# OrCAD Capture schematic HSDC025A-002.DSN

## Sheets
1 PAGE1: title: TUSB1064RNQEVM Block; rev: A; note: HSDC025A-002
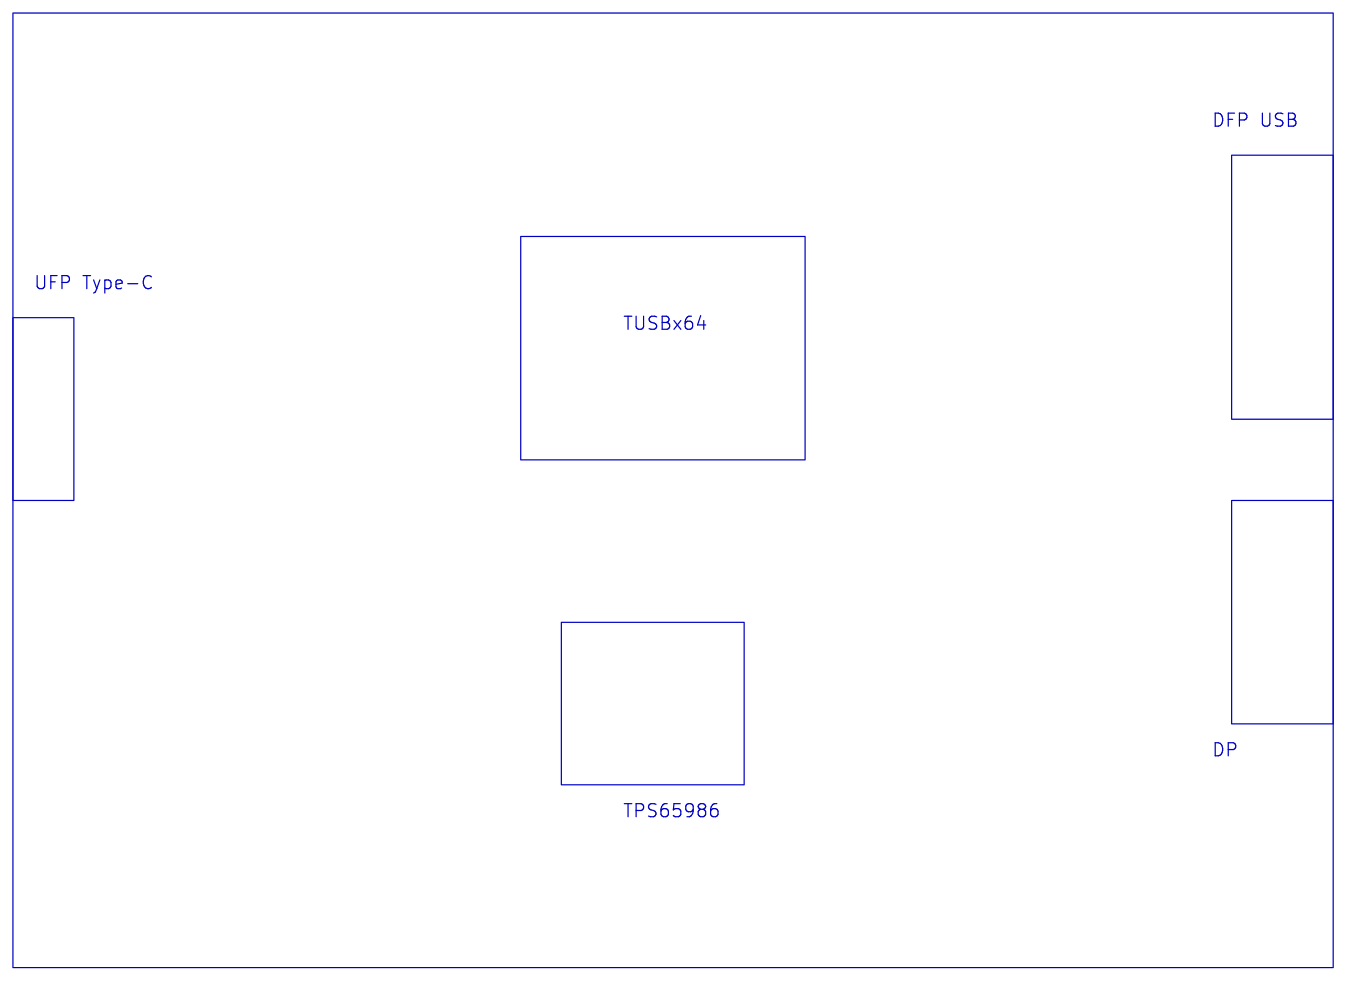
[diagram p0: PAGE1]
2 PAGE2: size B; title: TUSB1064RNQ
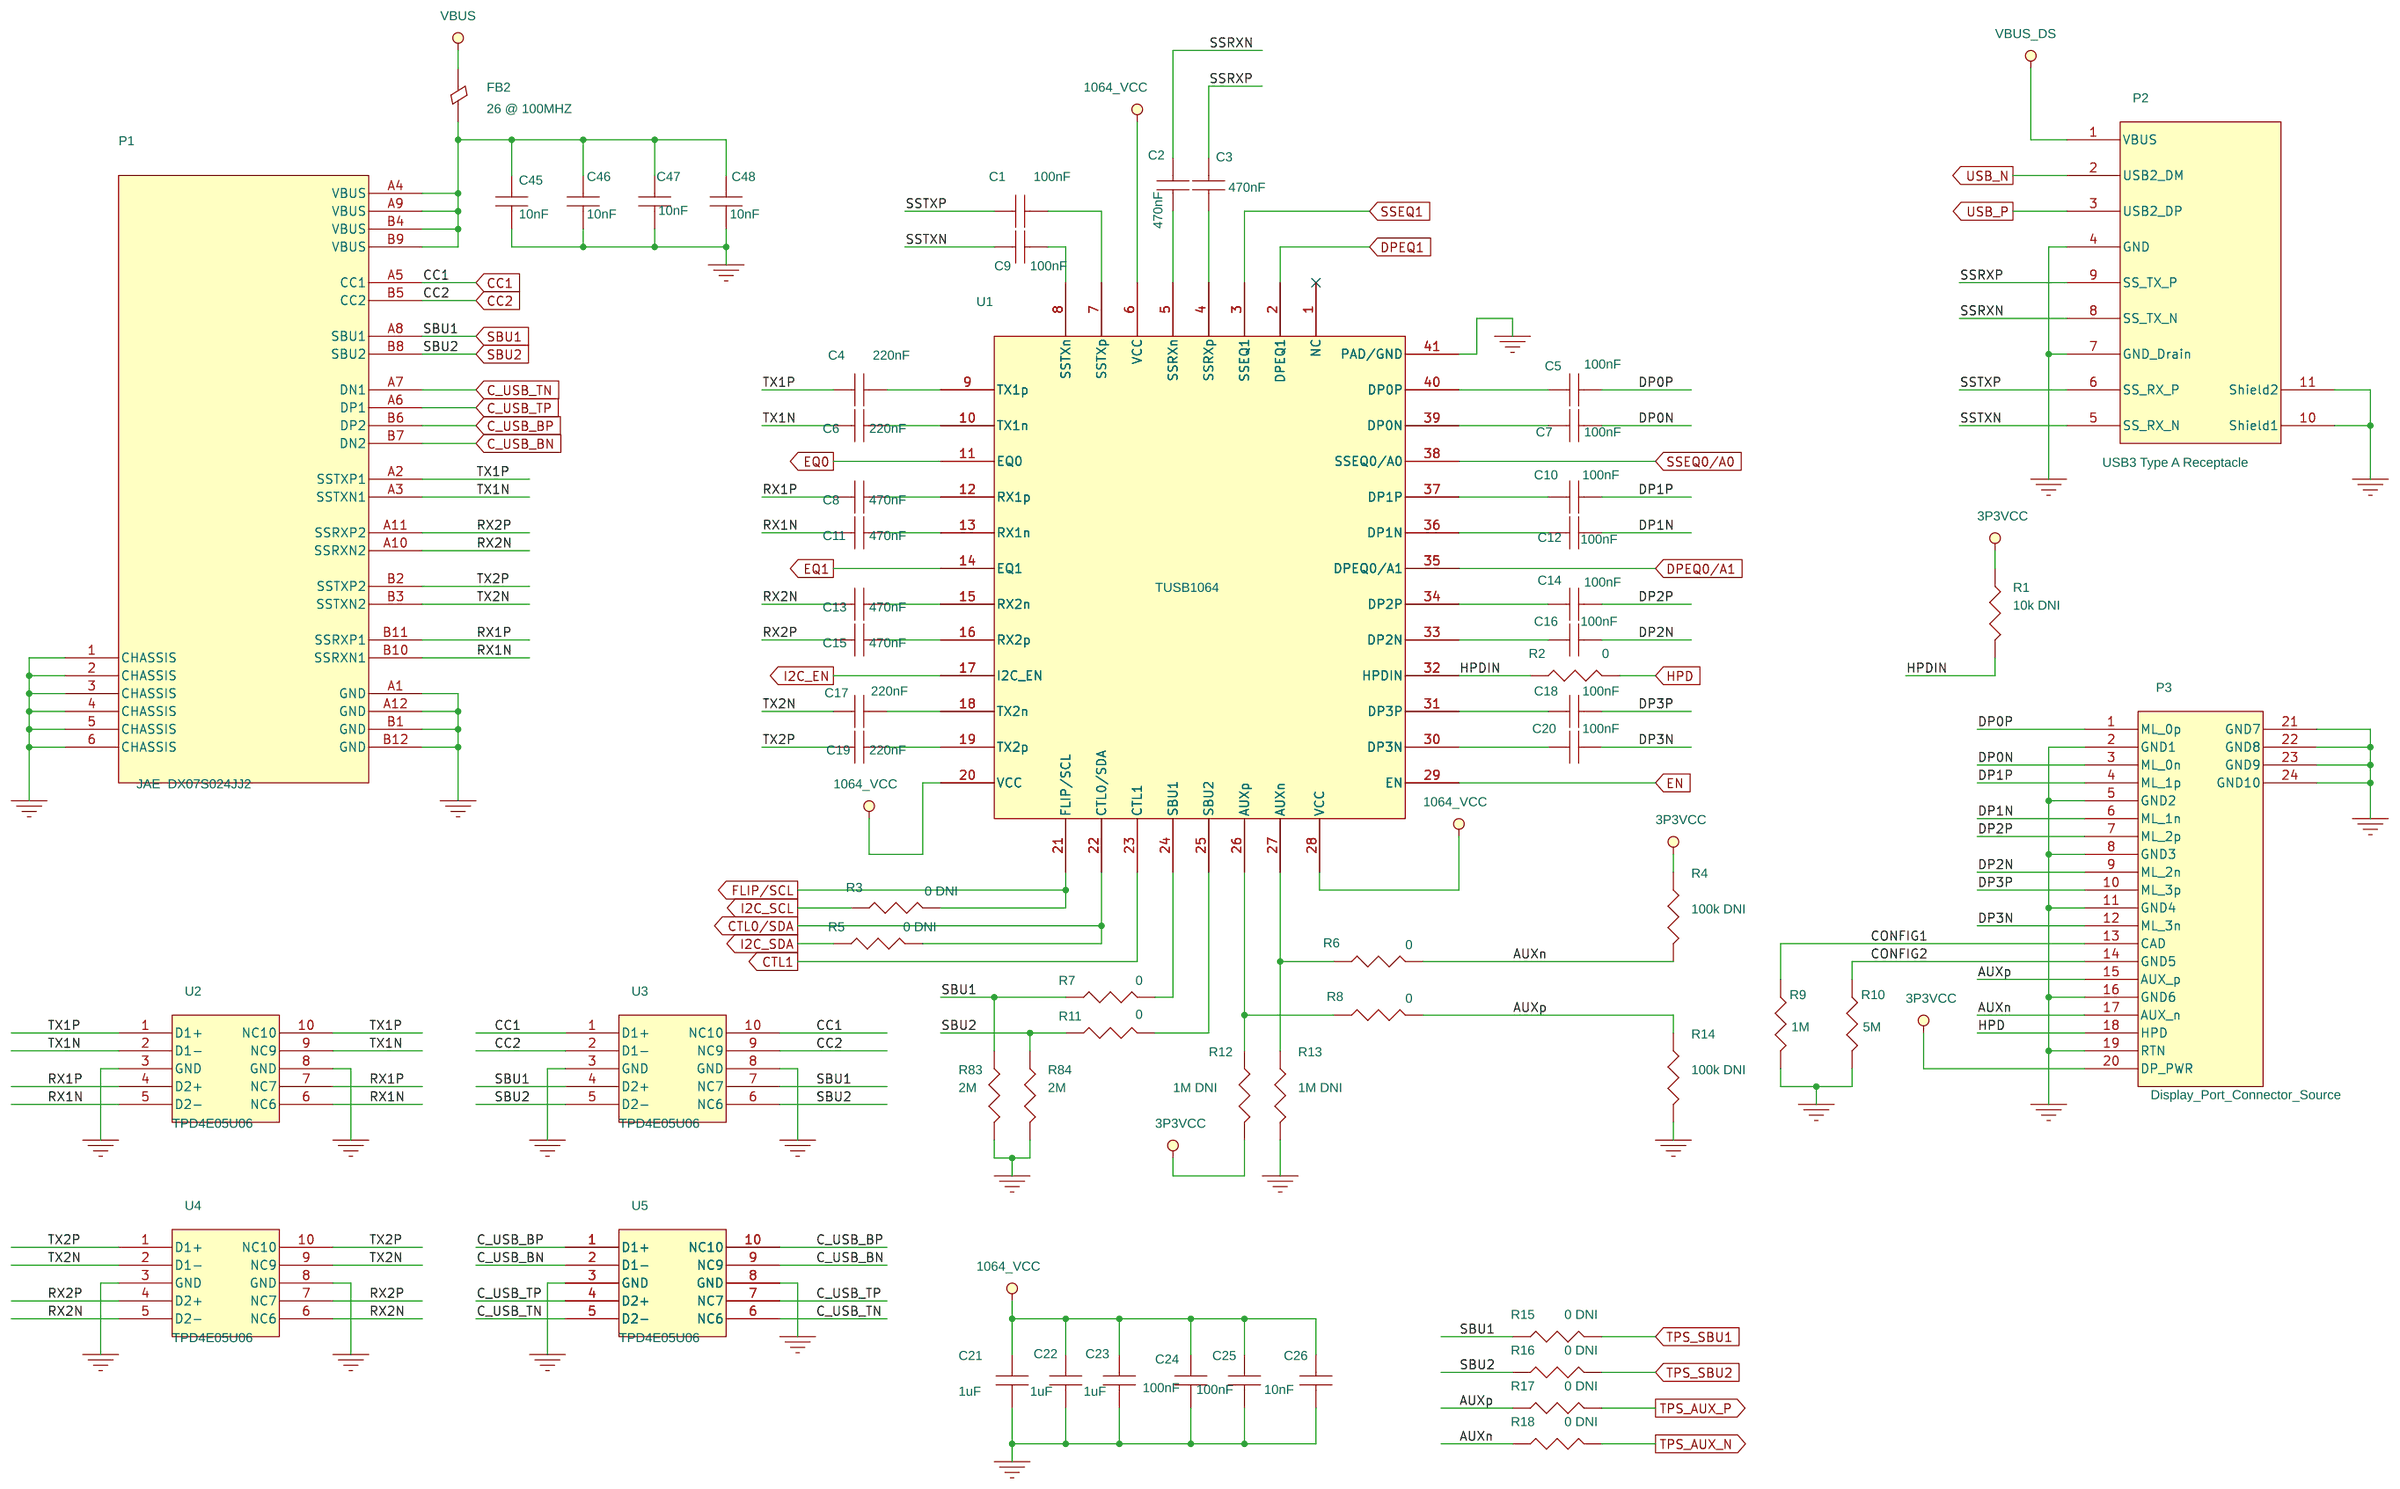
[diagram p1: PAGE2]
3 PAGE3: size B; title: TUSB1064 Config Pins
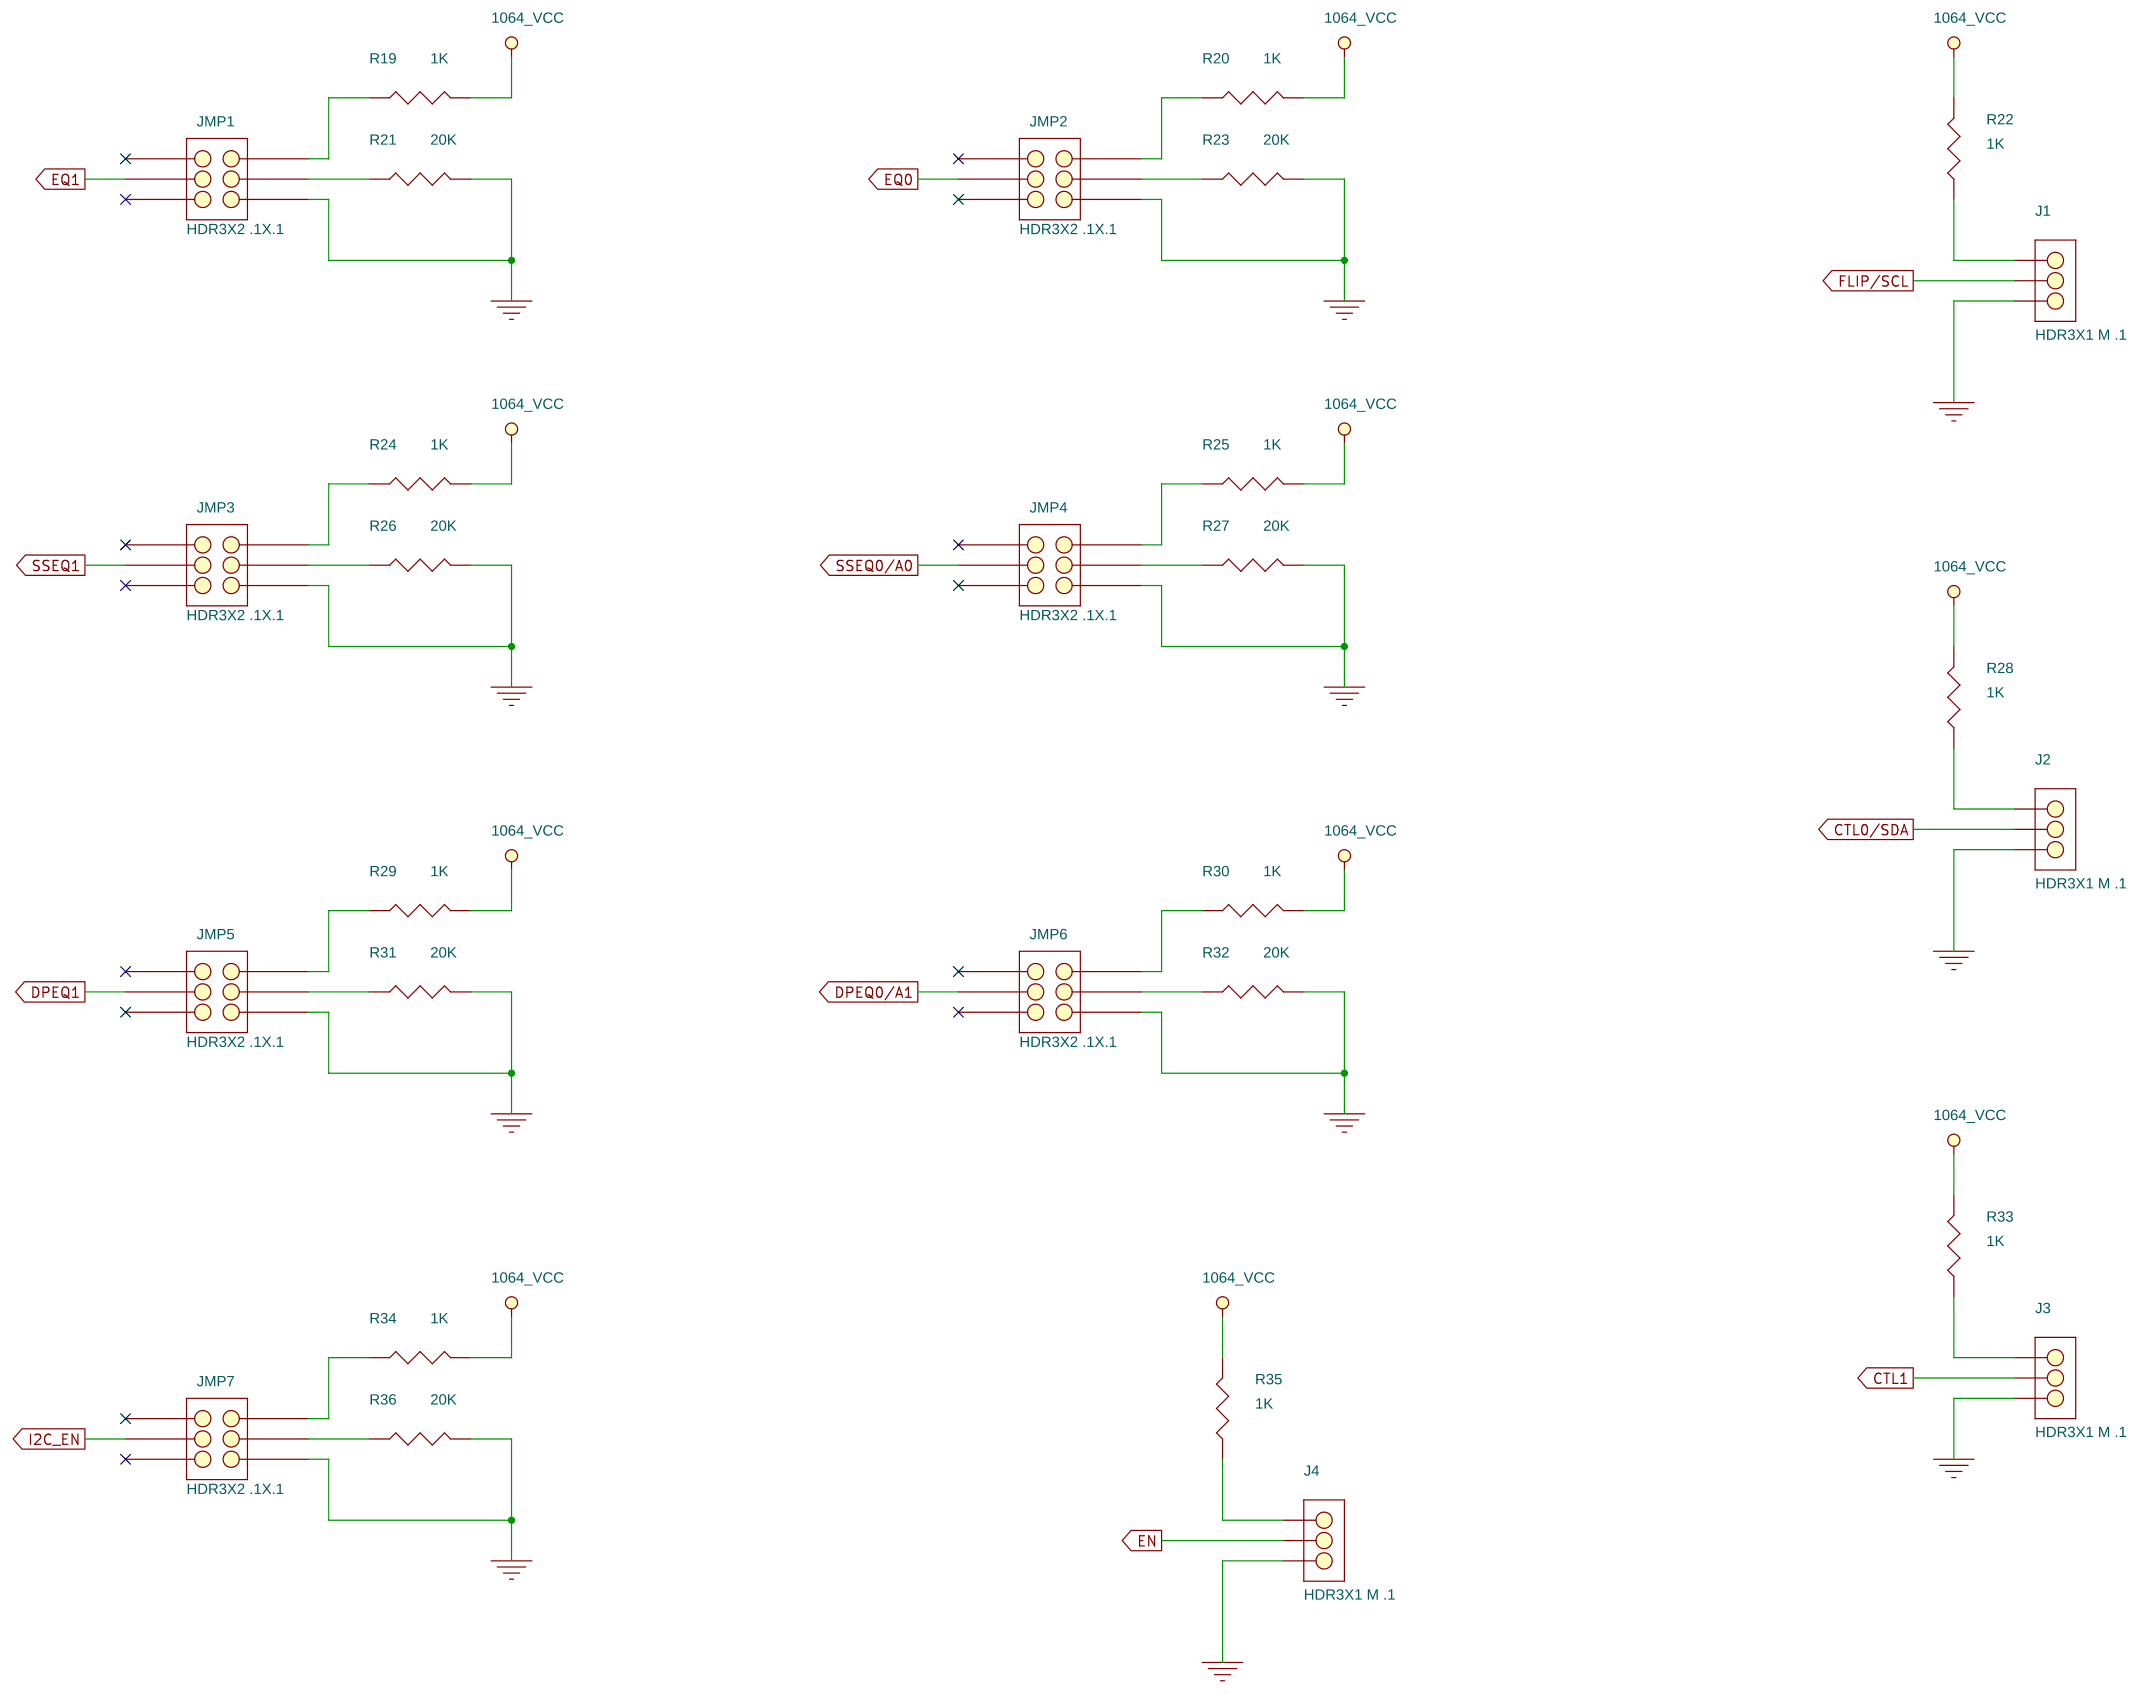
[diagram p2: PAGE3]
4 PAGE4: size C; title: TPS65986
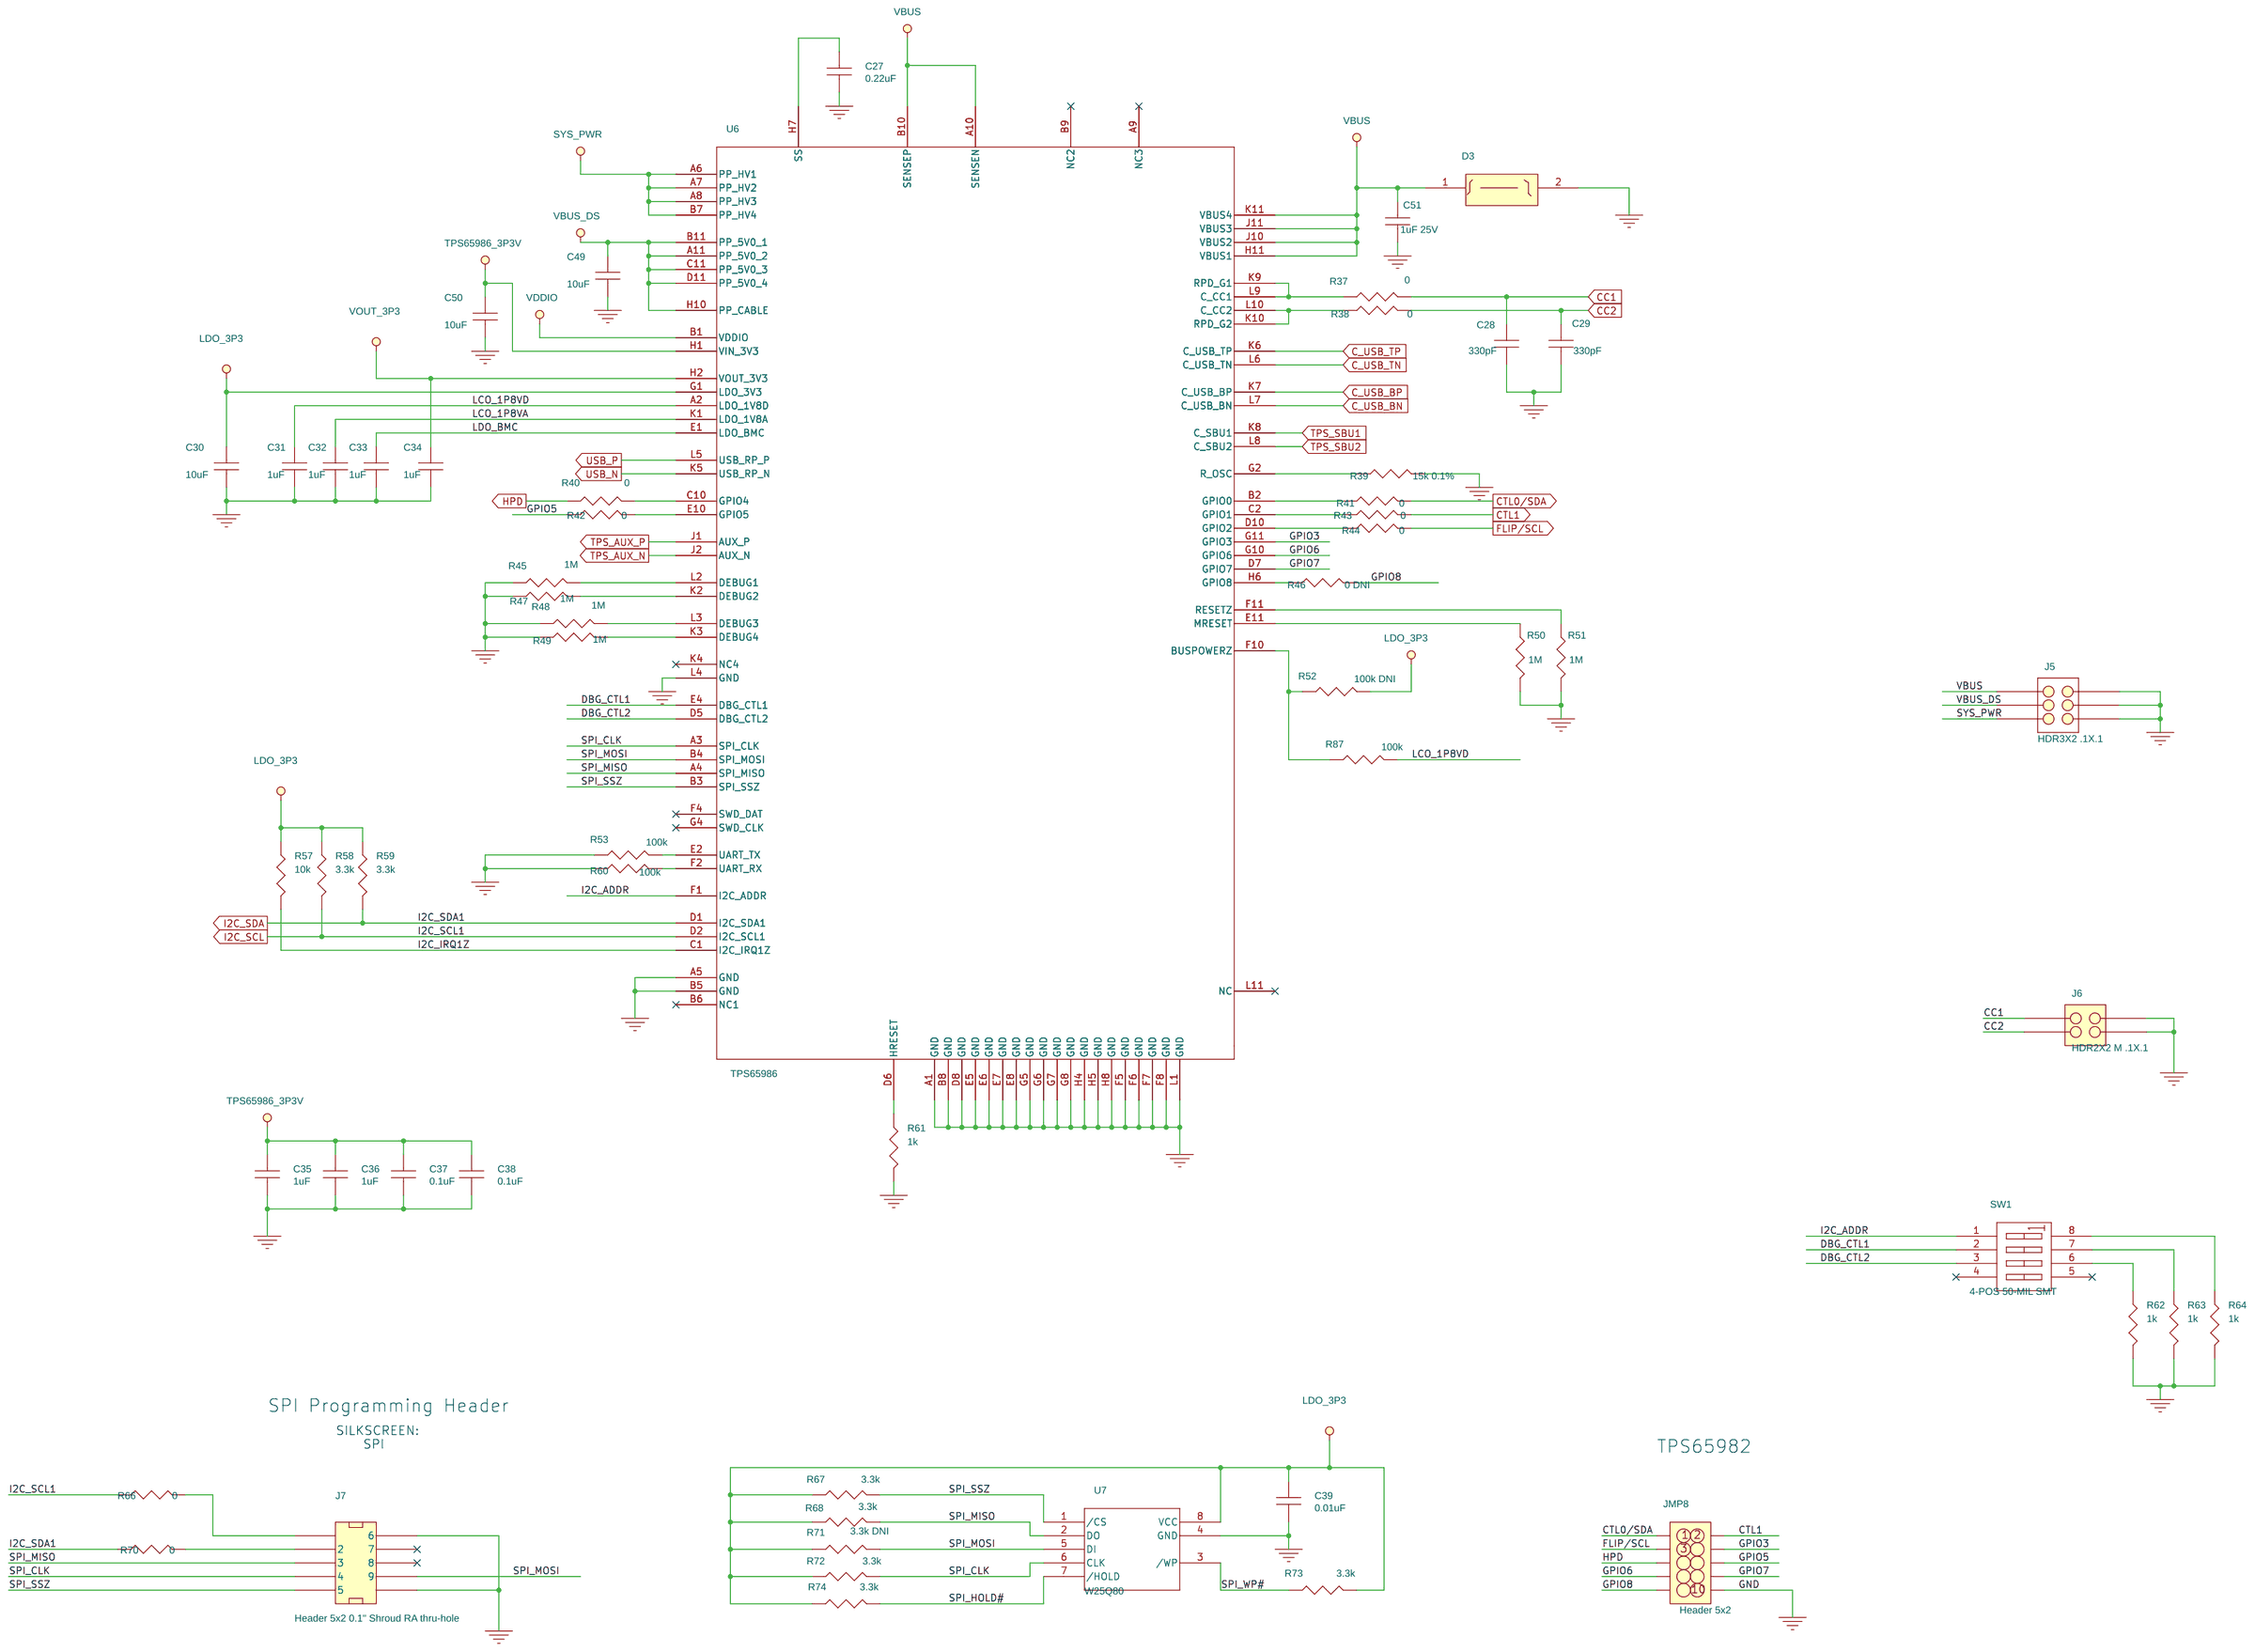
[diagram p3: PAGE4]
5 PAGE5: size C; title: Power
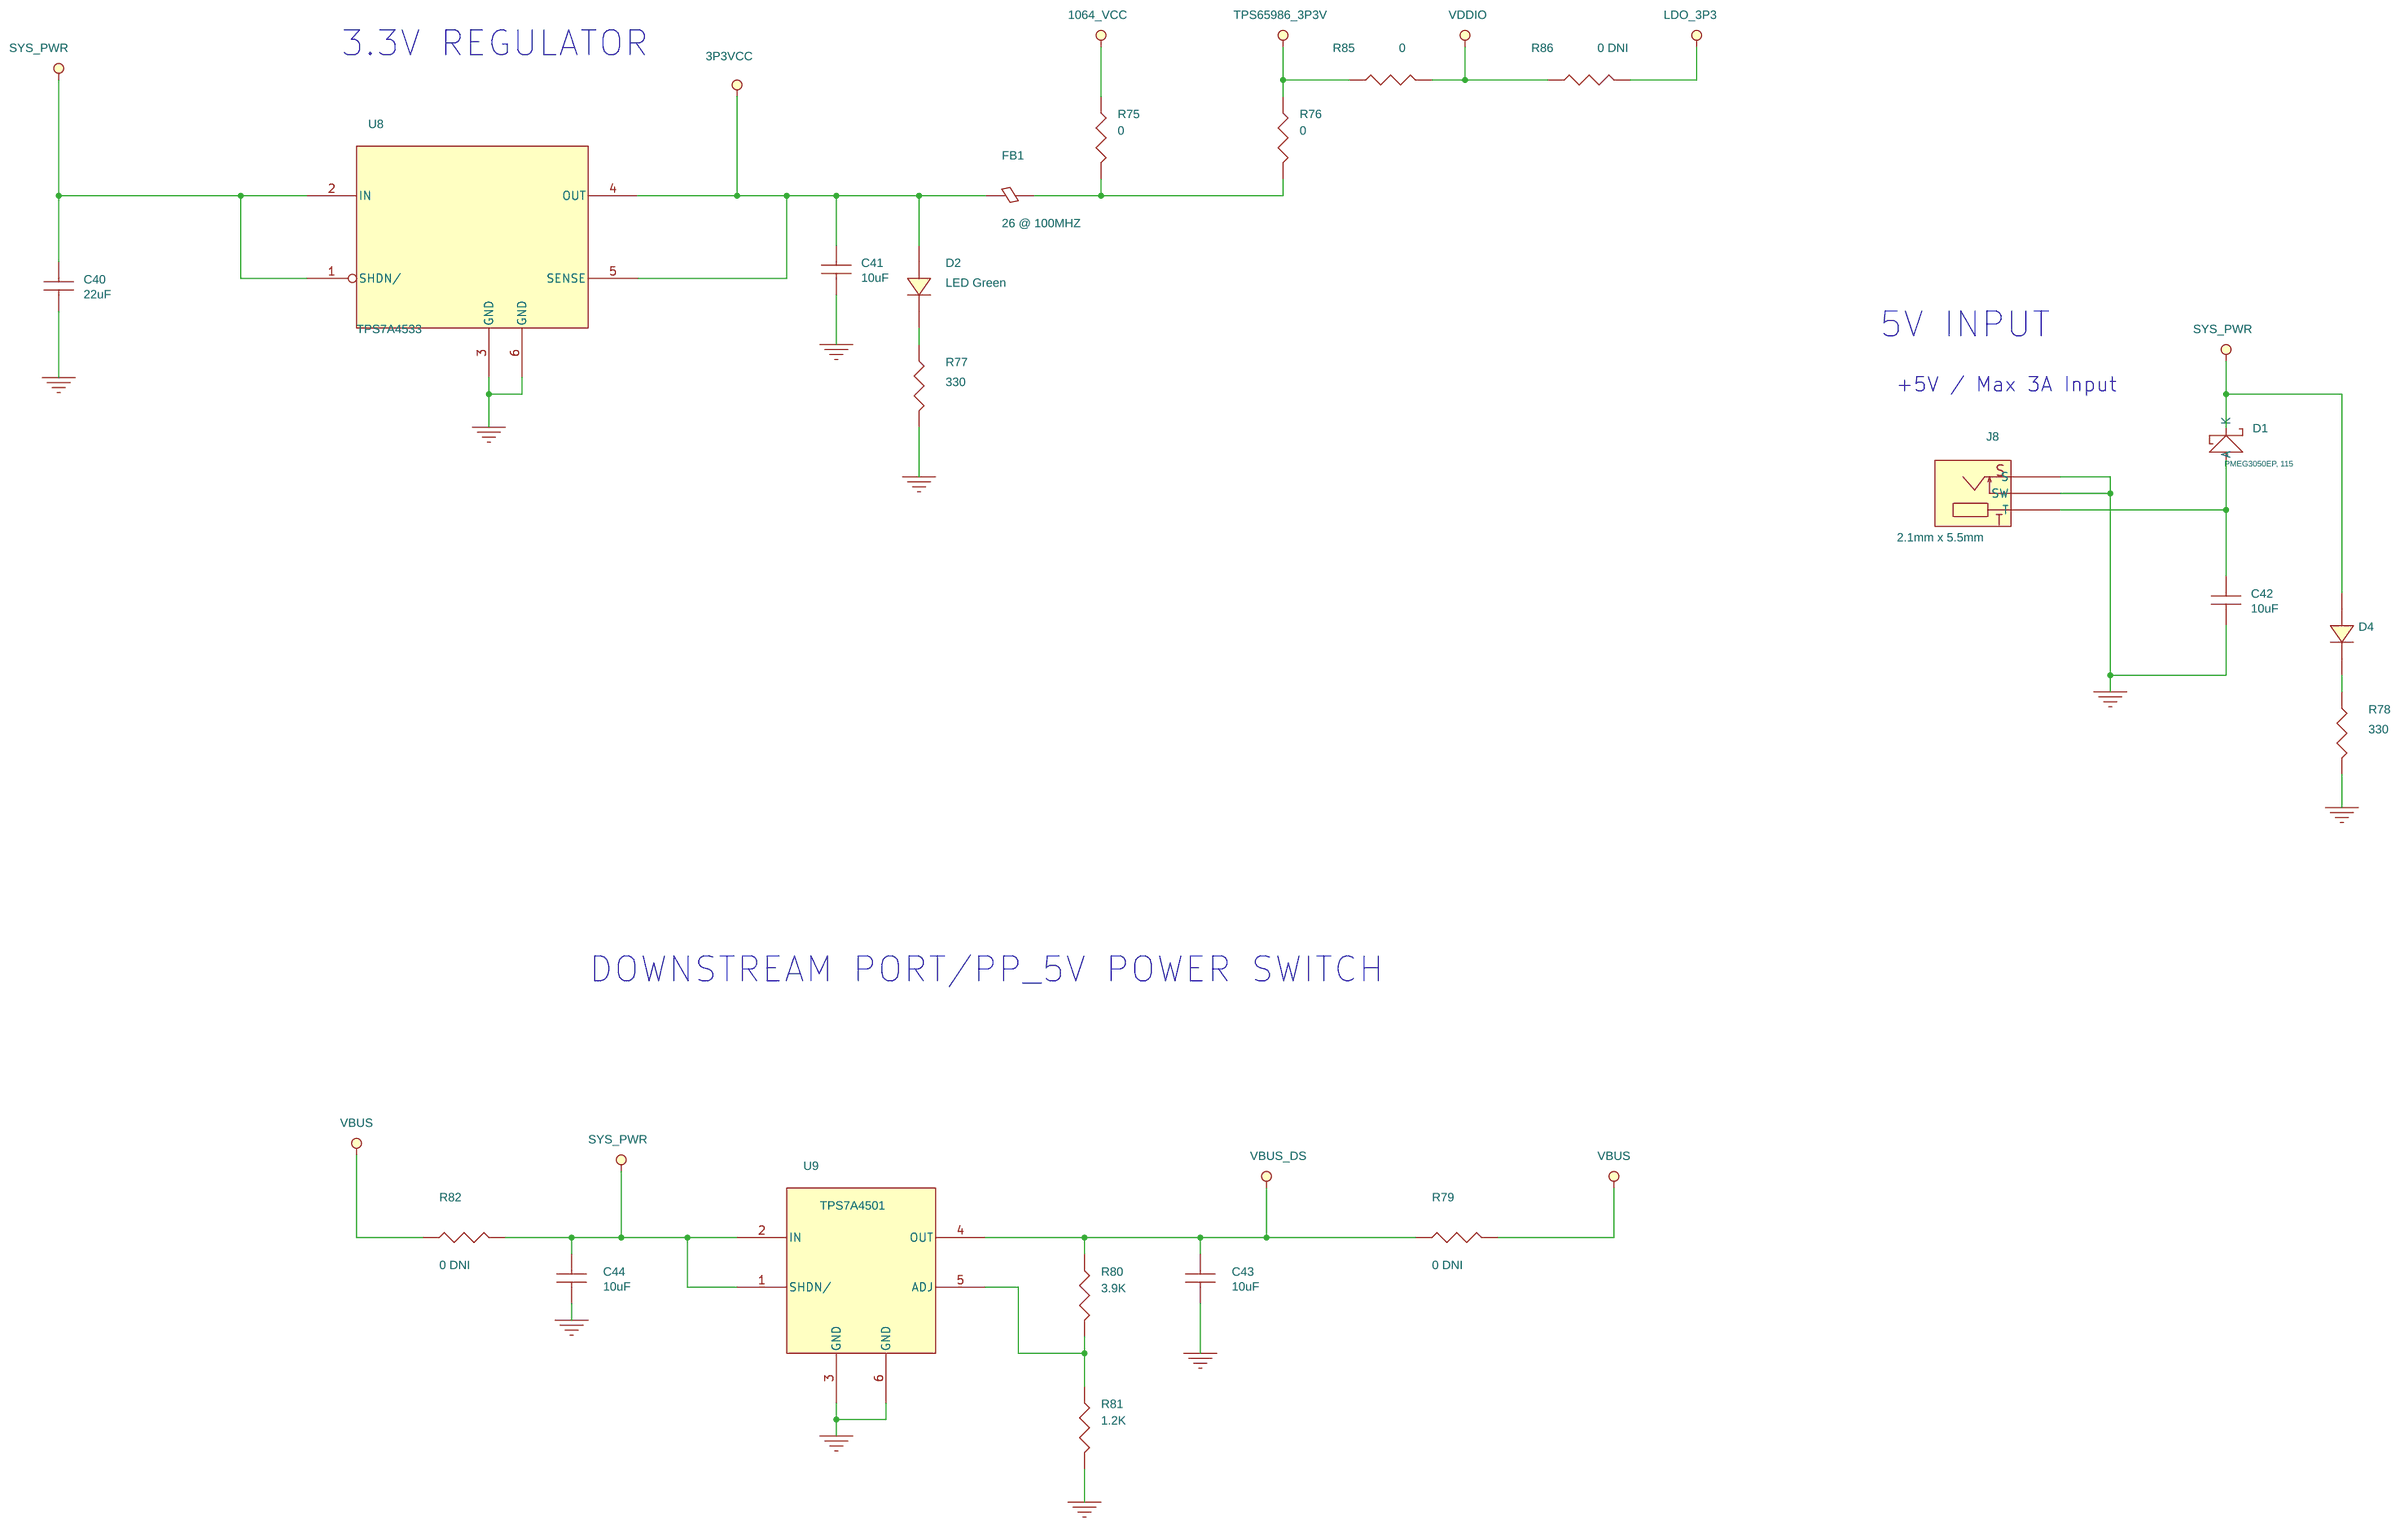
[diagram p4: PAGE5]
6 PAGE6: title: Hardware; rev: B
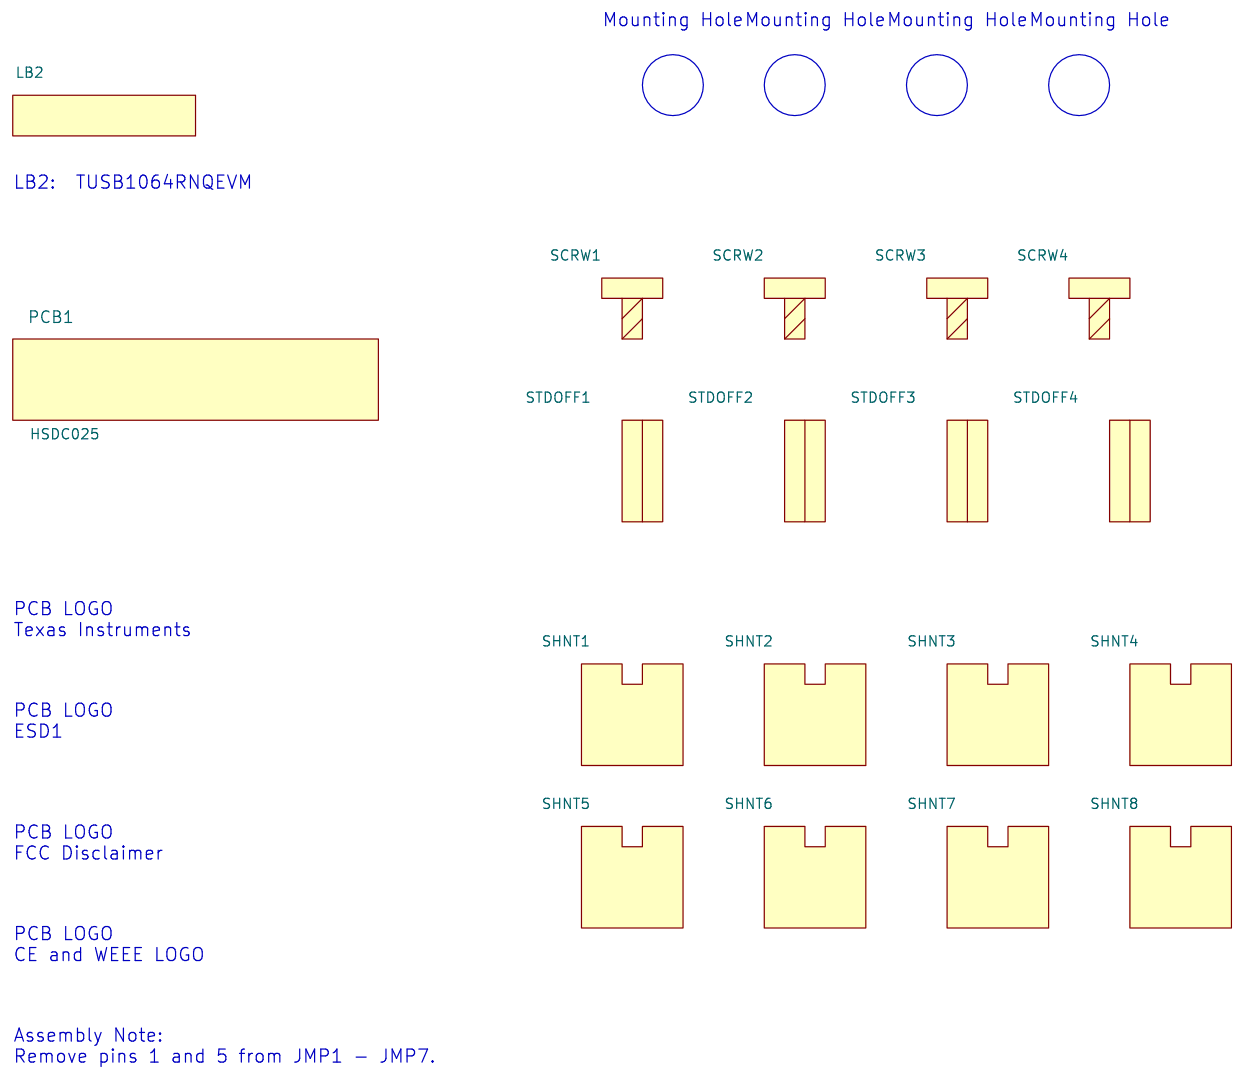
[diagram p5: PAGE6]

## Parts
sheet PAGE2
C1  100nF  [c0201]
C2  470nF  [c0201]
C3  470nF  [c0201]
C4  220nF  [c0201]
C5  100nF  [c0201]
C6  220nF  [c0201]
C7  100nF  [c0201]
C8  470nF  [c0201]
C9  100nF  [c0201]
C10  100nF  [c0201]
C11  470nF  [c0201]
C12  100nF  [c0201]
C13  470nF  [c0201]
C14  100nF  [c0201]
C15  470nF  [c0201]
C16  100nF  [c0201]
C17  220nF  [c0201]
C18  100nF  [c0201]
C19  220nF  [c0201]
C20  100nF  [c0201]
C21  1uF  [c0402]
C22  1uF  [c0402]
C23  1uF  [c0402]
C24  100nF  [c0402]
C25  100nF  [c0402]
C26  10nF  [c0402]
C45  10nF  [c0402]
C46  10nF  [c0402]
C47  10nF  [c0402]
C48  10nF  [c0402]
FB2  26 @ 100MHZ  [0603]
P1  JAE  DX07S024JJ2  [USB-C_SMRT_DX07S024JJ2]
P2  USB3 Type A Receptacle  [USB3_TYPEA]
P3  Display_Port_Connector_Source  [CON_DP_SD-47272-001]
R1  10k DNI  [r0402]
R2  0  [r0402]
R3  0 DNI  [r0402]
R4  100k DNI  [r0402]
R5  0 DNI  [r0402]
R6  0  [r0402]
R7  0  [r0402]
R8  0  [r0402]
R9  1M  [r0402]
R10  5M  [r0402]
R11  0  [r0402]
R12  1M DNI  [r0402]
R13  1M DNI  [r0402]
R14  100k DNI  [r0402]
R15  0 DNI  [r0402]
R16  0 DNI  [r0402]
R17  0 DNI  [r0402]
R18  0 DNI  [r0402]
R83  2M  [r0402]
R84  2M  [r0402]
U1  TUSB1064  [SKT_IRONWOOD_C14861_QFN-40]
U2  TPD4E05U06  [DQA]
U3  TPD4E05U06  [DQA]
U4  TPD4E05U06  [DQA]
U5  TPD4E05U06  [DQA]
sheet PAGE3
J1  HDR3X1 M .1  [HDR_THVT_1x3_100_M]
J2  HDR3X1 M .1  [HDR_THVT_1x3_100_M]
J3  HDR3X1 M .1  [HDR_THVT_1x3_100_M]
J4  HDR3X1 M .1  [HDR_THVT_1x3_100_M]
JMP1  HDR3X2 .1X.1  [HDR_THVT_2x3_100_M]
JMP2  HDR3X2 .1X.1  [HDR_THVT_2x3_100_M]
JMP3  HDR3X2 .1X.1  [HDR_THVT_2x3_100_M]
JMP4  HDR3X2 .1X.1  [HDR_THVT_2x3_100_M]
JMP5  HDR3X2 .1X.1  [HDR_THVT_2x3_100_M]
JMP6  HDR3X2 .1X.1  [HDR_THVT_2x3_100_M]
JMP7  HDR3X2 .1X.1  [HDR_THVT_2x3_100_M]
R19  1K  [r0402]
R20  1K  [r0402]
R21  20K  [r0402]
R22  1K  [r0402]
R23  20K  [r0402]
R24  1K  [r0402]
R25  1K  [r0402]
R26  20K  [r0402]
R27  20K  [r0402]
R28  1K  [r0402]
R29  1K  [r0402]
R30  1K  [r0402]
R31  20K  [r0402]
R32  20K  [r0402]
R33  1K  [r0402]
R34  1K  [r0402]
R35  1K  [r0402]
R36  20K  [r0402]
sheet PAGE4
C27  0.22uF  [c0402]
C28  330pF  [c0402]
C29  330pF  [c0402]
C30  10uF  [c0603]
C31  1uF  [c0402]
C32  1uF  [c0402]
C33  1uF  [c0402]
C34  1uF  [c0402]
C35  1uF  [c0402]
C36  1uF  [c0402]
C37  0.1uF  [c0402]
C38  0.1uF  [c0402]
C39  0.01uF  [c0402]
C49  10uF  [c0603]
C50  10uF  [c0603]
C51  1uF 25V  [c0603]
D3  TPD1E10B06  [DPY0002AA]
J5  HDR3X2 .1X.1  [HDR_THVT_2x3_100_M]
J6  HDR2X2 M .1X.1  [HDR_THVT_2x2_100]
J7  Header 5x2 0.1" Shroud RA thru-hole  [HDR_THRT_2X5_100]
JMP8  Header 5x2  [HDR_THVT_2x5_100]
R37  0  [r0201]
R38  0  [r0201]
R39  15k 0.1%  [r0402]
R40  0  [r0402]
R41  0  [r0402]
R42  0  [r0402]
R43  0  [r0402]
R44  0  [r0402]
R45  1M  [r0402]
R46  0 DNI  [r0402]
R47  1M  [r0402]
R48  1M  [r0402]
R49  1M  [r0402]
R50  1M  [r0402]
R51  1M  [r0402]
R52  100k DNI  [r0402]
R53  100k  [r0402]
R57  10k  [r0402]
R58  3.3k  [r0402]
R59  3.3k  [r0402]
R60  100k  [r0402]
R61  1k  [r0402]
R62  1k  [r0402]
R63  1k  [r0402]
R64  1k  [r0402]
R66  0  [r0402]
R67  3.3k  [r0402]
R68  3.3k  [r0402]
R70  0  [r0402]
R71  3.3k DNI  [r0402]
R72  3.3k  [r0402]
R73  3.3k  [r0402]
R74  3.3k  [r0402]
R87  100k  [r0402]
SW1  4-POS 50-MIL SMT  [sw_smvt_dip_4pos_8]
U6  TPS65986  [ZQZ_BGA_96]
U7  W25Q80  [SOIC_8_197x157_50]
sheet PAGE5
C40  22uF  [c1206]
C41  10uF  [c1206]
C42  10uF  [c1206]
C43  10uF  [c0603]
C44  10uF  [c0603]
D1  SCHOTTKY  [DO-214AA]
D2  LED Green  [0805]
D4  LED Green 0805  [0805]
FB1  26 @ 100MHZ  [0603]
J8  2.1mm x 5.5mm  [PJ-202AH]
R75  0  [r1206]
R76  0  [r1206]
R77  330  [r0402]
R78  330  [r0402]
R79  0 DNI  [r0805]
R80  3.9K  [r0402]
R81  1.2K  [r0402]
R82  0 DNI  [r0805]
R85  0  [r0402]
R86  0 DNI  [r0402]
U8  TPS7A4533  [DCQ_PDSO_6]
U9  TPS7A4501  [DCQ_PDSO_6]
sheet PAGE6
LB2  THD-47-478-10  [rectangle]
PCB1  HSDC025  [n/a]
SCRW1  NY PMS 440 005 PH  [screw]
SCRW2  NY PMS 440 005 PH  [screw]
SCRW3  NY PMS 440 005 PH  [screw]
SCRW4  NY PMS 440 005 PH  [screw]
SHNT1  QPC02SXGN-RC  [.1]
SHNT2  QPC02SXGN-RC  [.1]
SHNT3  QPC02SXGN-RC  [.1]
SHNT4  QPC02SXGN-RC  [.1]
SHNT5  QPC02SXGN-RC  [.1]
SHNT6  QPC02SXGN-RC  [.1]
SHNT7  QPC02SXGN-RC  [.1]
SHNT8  QPC02SXGN-RC  [.1]
STDOFF1  1902E  [Standoff]
STDOFF2  1902E  [Standoff]
STDOFF3  1902E  [Standoff]
STDOFF4  1902E  [Standoff]

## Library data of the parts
C1-C20 = cc0201
C21-C29 C31-C39 C45-C48 = cc0402
FB1 FB2 = FERRITE_BEAD
P1 = TypeC_JAE_TopMNT_0: Manufacturer: Jae; Manufacturer Part Number: DX07S024JJ2
P2 = USB_3.0_Type_A_Receptacle: Manufacturer: AMP; Manufacturer Part Number: 1932258-1
P3 = Display_Port_Connector_Source
R1-R36 R39-R53 R57-R64 R66-R68 R70-R74 R80 R81 R83-R87 = r0402
U1 = TUSB1064
U2-U5 = TPD4E05U06
J1-J4 = HDR3X1_M_.1
J5 JMP1-JMP7 = HDR3X2_M_.1X.1
C30 C43 C44 C49-C51 = cc0603
D3 = TPD1E10B06
J6 = HDR2X2_M_.1X.1
J7 = CONN_PCB_5x2-S: Digi-Key Part Number: 3M15452-ND; Manufacturer: 3M; Manufacturer Part Number: 30310-5002HB
JMP8 = Header_5x2: Manufacturer: AMP; Manufacturer Part Number: 67997-410HLF
R37 R38 = r0201
SW1 = SW_DIP-4: Digi-Key PN: CKN9502CT-ND; Digi-Key Part Number: CKN9502CT-ND; Manuf: C&K(ITT-CANNON); Manuf PN: TDA04H0SB1R; Manufacturer: C&K(ITT-CANNON); Manufacturer Part Number: TDA04H0SB1R; Manufacturer's Part Number: TDA04H0SB1R; Vendor: Digi-Key; Vendor Part Number: CKN9502CT-ND
U6 = TPS65982_0: Manufacturer: Texas Instruments; Manufacturer Part Number: TPS65982; Manufacturer's Part Number: TPS65982
U7 = W25Q80SSI: Digi-Key Part Number: W25Q80DVSNIG-ND; Manufacturer Part Number: W25Q80DVSNIG
C40-C42 = CAP_NP
D1 = SCHOTTKY_2: Diode; $SEC: 1; CDS_LIB: diode; DEVICE_NAME: PMEG3050EP, 115; Digi-Key Part Number: 568-6753-2-ND; Manufacturer: NXP; Manufacturer Part Number: PMEG3050EP,115; Manufacturer's Part Number: PMEG3050EP,115; PHYS_PAGE: 1; ROT: 0; TOLERANCE: NA; VER: 1; VOLTAGE: 10V; XY: (-1750,3700)
D2 D4 = DIODE: Manuf: Lumex; Manuf PN: SML-LX0805GC-TR
J8 = BNC_2: MANUF: CUI STACK; PART_NUMBER: 5V_SUPPLY; TI_Silktext: 5V_SUPPLY
R75 R76 = r1206
R77 R78 = R: Tolerance: 5%
R79 R82 = r0805
U8 = TPS79633KTT_2: Manuf PN: TPS79633KTT
U9 = TPS7A4501
LB2 = Label
PCB1 = PCB: Manufacturer: Any
SCRW1-SCRW4 = Screw_40x.5_Nylon
SHNT1-SHNT8 = Shunt
STDOFF1-STDOFF4 = Standoff

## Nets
GND: C21.2 C22.2 C23.2 C24.2 C25.2 C26.2 C27.2 C28.2 C29.2 C30.2 C31.2 C32.2 C33.2 C34.2 C35.2 C36.2 C37.2 C38.2 C39.2 C40.2 C41.2 C42.2 C43.2 C44.2 C45.2 C46.2 C47.2 C48.2 C49.2 C50.2 C51.2 D3.2 J1.3 J2.3 J3.3 J4.3 J5.2 J5.4 J5.6 J6.2 J6.4 J7.2(6) J7.10 J8.2(S) J8.3(SW) JMP1.6 JMP2.6 JMP3.6 JMP4.6 JMP5.6 JMP6.6 JMP7.6 JMP8.10 P1.1(CHASSIS) P1.2(CHASSIS) P1.3(CHASSIS) P1.4(CHASSIS) P1.5(CHASSIS) P1.6(CHASSIS) P1.A1(GND) P1.A12(GND) P1.B1(GND) P1.B12(GND) P2.4(GND) P2.7(GND_Drain) P2.10(Shield1) P2.11(Shield2) P3.2(GND1) P3.5(GND2) P3.8(GND3) P3.11(GND4) P3.16(GND6) P3.19(RTN) P3.21(GND7) P3.22(GND8) P3.23(GND9) P3.24(GND10) R9.2 R10.2 R13.2 R14.2 R21.2 R23.2 R26.2 R27.2 R31.2 R32.2 R36.2 R39.2 R45.1 R47.1 R48.1 R49.1 R50.2 R51.2 R53.1 R60.1 R61.2 R62.2 R63.2 R64.2 R77.2 R78.2 R81.2 R83.2 R84.2 U1.41(PAD/GND) U2.3(GND) U2.8(GND) U3.3(GND) U3.8(GND) U4.3(GND) U4.8(GND) U5.3(GND) U5.8(GND) U6.A1(GND) U6.A5(GND) U6.B5(GND) U6.B8(GND) U6.D8(GND) U6.E5(GND) U6.E6(GND) U6.E7(GND) U6.E8(GND) U6.F5(GND) U6.F6(GND) U6.F7(GND) U6.F8(GND) U6.G5(GND) U6.G6(GND) U6.G7(GND) U6.G8(GND) U6.H4(GND) U6.H5(GND) U6.H8(GND) U6.L1(GND) U6.L4(GND) U7.4(GND) U8.3(GND) U8.6(GND) U9.3(GND) U9.6(GND)
VBUS: C51.1 D3.1 FB2.2 J5.1 R79.2 R82.1 U6.A10(SENSEN) U6.B10(SENSEP) U6.H11(VBUS1) U6.J10(VBUS2) U6.J11(VBUS3) U6.K11(VBUS4)
VBUS_DS: C43.1 C49.1 J5.3 P2.1(VBUS) R79.1 R80.1 U6.A11(PP_5V0_2) U6.B11(PP_5V0_1) U6.C11(PP_5V0_3) U6.D11(PP_5V0_4) U6.H10(PP_CABLE) U9.4(OUT)
VDDIO: R85.2 R86.1 U6.B1(VDDIO)
3P3VCC: C41.1 D2.1(A) FB1.2 P3.20(DP_PWR) R1.1 R4.1 R12.2 U8.4(OUT) U8.5(SENSE)
1064_VCC: C21.1 C22.1 C23.1 C24.1 C25.1 C26.1 R19.2 R20.2 R22.2 R24.2 R25.2 R28.2 R29.2 R30.2 R33.2 R34.2 R35.2 R75.1 U1.6(VCC) U1.20(VCC) U1.28(VCC)
AUXn: P3.17(AUX_n) R4.2 R6.2 R18.1
AUXp: P3.15(AUX_p) R8.2 R14.1 R17.1
C_USB_BN: P1.B7(DN2) U5.2(D1-) U5.9(NC9) U6.L7(C_USB_BN)
C_USB_BP: P1.B6(DP2) U5.1(D1+) U5.10(NC10) U6.K7(C_USB_BP)
C_USB_TN: P1.A7(DN1) U5.5(D2-) U5.6(NC6) U6.L6(C_USB_TN)
C_USB_TP: P1.A6(DP1) U5.4(D2+) U5.7(NC7) U6.K6(C_USB_TP)
CC1: C28.1 J6.1 P1.A5(CC1) R37.2 U3.1(D1+) U3.10(NC10)
CC2: C29.1 J6.3 P1.B5(CC2) R38.2 U3.2(D1-) U3.9(NC9)
CONFIG1: P3.13(CAD) R9.1
CONFIG2: P3.14(GND5) R10.1
CTL0/SDA: J2.2 JMP8.1 R5.2 R41.2 U1.22(CTL0/SDA)
CTL1: J3.2 JMP8.2 R43.2 U1.23(CTL1)
DBG_CTL1: SW1.2 U6.E4(DBG_CTL1)
DBG_CTL2: SW1.3 U6.D5(DBG_CTL2)
DP0N: C7.2 P3.3(ML_0n)
DP0P: C5.2 P3.1(ML_0p)
DP1N: C12.2 P3.6(ML_1n)
DP1P: C10.2 P3.4(ML_1p)
DP2N: C16.2 P3.9(ML_2n)
DP2P: C14.2 P3.7(ML_2p)
DP3N: C20.2 P3.12(ML_3n)
DP3P: C18.2 P3.10(ML_3p)
DPEQ0/A1: JMP6.3 U1.35(DPEQ0/A1)
DPEQ1: JMP5.3 U1.2(DPEQ1)
EN: J4.2 U1.29(EN)
EQ0: JMP2.3 U1.11(EQ0)
EQ1: JMP1.3 U1.14(EQ1)
FLIP/SCL: J1.2 JMP8.3 R3.2 R44.2 U1.21(FLIP/SCL)
GPIO3: JMP8.4 U6.G11(GPIO3)
GPIO5: JMP8.6 R42.1
GPIO6: JMP8.7 U6.G10(GPIO6)
GPIO7: JMP8.8 U6.D7(GPIO7)
GPIO8: JMP8.9 R46.2
HPD: JMP8.5 P3.18(HPD) R2.2 R40.1
HPDIN: R1.2 R2.1 U1.32(HPDIN)
I2C_ADDR: SW1.1 U6.F1(I2C_ADDR)
I2C_EN: JMP7.3 U1.17(I2C_EN)
I2C_IRQ1Z: R57.2 U6.C1(I2C_IRQ1Z)
I2C_SCL: R3.1 R58.2 R66.1 U6.D2(I2C_SCL1)
I2C_SDA: R5.1 R59.2 R70.1 U6.D1(I2C_SDA1)
LCO_1P8VA: C32.1 U6.K1(LDO_1V8A)
LCO_1P8VD: C31.1 R87.2 U6.A2(LDO_1V8D)
LDO_3P3: C30.1 C39.1 R52.2 R57.1 R58.1 R59.1 R67.1 R68.1 R71.1 R72.1 R73.2 R74.1 R86.2 U6.G1(LDO_3V3) U7.8(VCC)
LDO_BMC: C33.1 U6.E1(LDO_BMC)
RX1N: C11.1 P1.B10(SSRXN1) U2.5(D2-) U2.6(NC6)
RX1P: C8.1 P1.B11(SSRXP1) U2.4(D2+) U2.7(NC7)
RX2N: C13.1 P1.A10(SSRXN2) U4.5(D2-) U4.6(NC6)
RX2P: C15.1 P1.A11(SSRXP2) U4.4(D2+) U4.7(NC7)
SBU1: P1.A8(SBU1) R7.1 R15.1 R83.1 U3.4(D2+) U3.7(NC7)
SBU2: P1.B8(SBU2) R11.1 R16.1 R84.1 U3.5(D2-) U3.6(NC6)
SPI_CLK: J7.7(4) R72.2 U6.A3(SPI_CLK) U7.6(CLK)
SPI_HOLD#: R74.2 U7.7(/HOLD)
SPI_MISO: J7.5(3) R68.2 U6.A4(SPI_MISO) U7.2(DO)
SPI_MOSI: J7.8(9) R71.2 U6.B4(SPI_MOSI) U7.5(DI)
SPI_SSZ: J7.9(5) R67.2 U6.B3(SPI_SSZ) U7.1(/CS)
SPI_WP#: R73.1 U7.3(/WP)
SSEQ0/A0: JMP4.3 U1.38(SSEQ0/A0)
SSEQ1: JMP3.3 U1.3(SSEQ1)
SSRXN: C2.2 P2.8(SS_TX_N)
SSRXP: C3.2 P2.9(SS_TX_P)
SSTXN: C9.1 P2.5(SS_RX_N)
SSTXP: C1.1 P2.6(SS_RX_P)
SYS_PWR: C40.1 C44.1 D1.1(K) D4.1(A) J5.5 R82.2 U6.A6(PP_HV1) U6.A7(PP_HV2) U6.A8(PP_HV3) U6.B7(PP_HV4) U8.1(SHDN/) U8.2(IN) U9.1(SHDN/) U9.2(IN)
TPS65986_3P3V: C35.1 C36.1 C37.1 C38.1 C50.1 R76.1 R85.1 U6.H1(VIN_3V3)
TPS_AUX_N: R18.2 U6.J2(AUX_N)
TPS_AUX_P: R17.2 U6.J1(AUX_P)
TPS_SBU1: R15.2 U6.K8(C_SBU1)
TPS_SBU2: R16.2 U6.L8(C_SBU2)
TX1N: C6.1 P1.A3(SSTXN1) U2.2(D1-) U2.9(NC9)
TX1P: C4.1 P1.A2(SSTXP1) U2.1(D1+) U2.10(NC10)
TX2N: C17.1 P1.B3(SSTXN2) U4.2(D1-) U4.9(NC9)
TX2P: C19.1 P1.B2(SSTXP2) U4.1(D1+) U4.10(NC10)
USB_N: P2.2(USB2_DM) U6.K5(USB_RP_N)
USB_P: P2.3(USB2_DP) U6.L5(USB_RP_P)
VOUT_3P3: C34.1 U6.H2(VOUT_3V3)
N51428: C45.1 C46.1 C47.1 C48.1 FB2.1 P1.A4(VBUS) P1.A9(VBUS) P1.B4(VBUS) P1.B9(VBUS)
N52896: C4.2 U1.9(TX1p)
N52900: C6.2 U1.10(TX1n)
N52912: C17.2 U1.18(TX2n)
N52916: C19.2 U1.19(TX2p)
N53113: C2.1 U1.5(SSRXn)
N53117: C3.1 U1.4(SSRXp)
N53375: C5.1 U1.40(DP0P)
N53379: C7.1 U1.39(DP0N)
N53383: C10.1 U1.37(DP1P)
N53387: C12.1 U1.36(DP1N)
N53391: C14.1 U1.34(DP2P)
N53395: C16.1 U1.33(DP2N)
N53399: C18.1 U1.31(DP3P)
N53403: C20.1 U1.30(DP3N)
N54909: R37.1 U6.K9(RPD_G1) U6.L9(C_CC1)
N54981: R38.1 U6.K10(RPD_G2) U6.L10(C_CC2)
N60753: J1.1 R22.1
N61165: J2.1 R28.1
N61173: JMP3.4 R26.1
N61517: J3.1 R33.1
N61661: J4.1 R35.1
N62024: R6.1 R13.1 U1.27(AUXn)
N62031: R8.1 R12.1 U1.26(AUXp)
N62627: R11.2 U1.25(SBU2)
N62636: R7.2 U1.24(SBU1)
N63203: R41.1 U6.B2(GPIO0)
N63233: R43.1 U6.C2(GPIO1)
N63241: R44.1 U6.D10(GPIO2)
N63249: R40.2 U6.C10(GPIO4)
N73513: C1.2 U1.7(SSTXp)
N73520: C9.2 U1.8(SSTXn)
N75829: R42.2 U6.E10(GPIO5)
N78382: J7.1 R66.2
N78490: J7.3(2) R70.2
N79273: R49.2 U6.K3(DEBUG4)
N79277: R48.2 U6.L3(DEBUG3)
N79281: R47.2 U6.K2(DEBUG2)
N79285: R45.2 U6.L2(DEBUG1)
N80574: R51.1 U6.F11(RESETZ)
N80581: R50.1 U6.E11(MRESET)
N81425: R39.1 U6.G2(R_OSC)
N85567: R53.2 U6.E2(UART_TX)
N85571: R60.2 U6.F2(UART_RX)
N88590: R52.1 R87.1 U6.F10(BUSPOWERZ)
N89051: R62.1 SW1.6
N89058: R63.1 SW1.7
N89065: R64.1 SW1.8
N92164: R61.1 U6.D6(HRESET)
N95070: C27.1 U6.H7(SS)
N98885: D2.2(K) R77.1
N16697259: C42.1 D1.2(A) J8.1(T)
N16698171: FB1.1 R75.2 R76.2
N16698282: R46.1 U6.H6(GPIO8)
N16700173: D4.2(K) R78.1
N16705873: C8.2 U1.12(RX1p)
N16705894: C11.2 U1.13(RX1n)
N16705898: C13.2 U1.15(RX2n)
N16705902: C15.2 U1.16(RX2p)
N16750118: R80.2 R81.1 U9.5(ADJ)
N16816893: JMP1.2 R19.1
N16816902: JMP1.4 R21.1
N16816999: JMP3.2 R24.1
N16817208: JMP5.2 R29.1
N16817217: JMP5.4 R31.1
N16817279: JMP7.2 R34.1
N16817288: JMP7.4 R36.1
N16817349: JMP6.2 R30.1
N16817418: JMP6.4 R32.1
N16817489: JMP4.4 R27.1
N16817492: JMP4.2 R25.1
N16817504: JMP2.2 R20.1
N16817513: JMP2.4 R23.1

Not connected (* = marked no-connect by the designer): J7 4(7)* 6(8)*; JMP1 1* 5*; JMP2 1* 5*; JMP3 1* 5*; JMP4 1* 5*; JMP5 1* 5*; JMP6 1* 5*; JMP7 1* 5*; SW1 4* 5*; U1 1(NC)*; U6 A9(NC3)* B6(NC1)* B9(NC2)* F4(SWD_DAT)* G4(SWD_CLK)* K4(NC4)* L11(NC)*

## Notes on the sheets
sheet 1
- DFP USB
- UFP Type-C
- TUSBx64
- DP
- TPS65986
sheet 4
- SPI Programming Header
- SILKSCREEN:
- SPI
- TPS65982
sheet 5
- 3.3V REGULATOR
- 5V INPUT
- +5V / Max 3A Input
- DOWNSTREAM PORT/PP_5V POWER SWITCH
sheet 6
- Mounting Hole
- Mounting Hole
- Mounting Hole
- Mounting Hole
- LB2:  TUSB1064RNQEVM
- PCB LOGO
  Texas Instruments
- PCB LOGO
  ESD1
- PCB LOGO
  FCC Disclaimer
- PCB LOGO
  CE and WEEE LOGO
- Assembly Note:
  Remove pins 1 and 5 from JMP1 - JMP7.
